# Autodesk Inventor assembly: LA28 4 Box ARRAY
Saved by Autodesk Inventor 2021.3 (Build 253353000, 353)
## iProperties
Created: 2023-01
Part Number: LA28 4 Box ARRAY
Document SubType Name: Assembly
Designer: AdminForWorker
Title: LA28 4 Box ARRAY v2
Author: AdminForWorker
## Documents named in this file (3)
- c:\worker\convert-fusion-r08-cosv3\tmp\job-1\2\output\files\38fcaebe-cb34-4e03-bd92-f432653286df\9825a87c-4a88-42d5-add3-ba31ce4555a8.iam
- c:\worker\convert-fusion-r08-cosv3\tmp\job-1\2\output\files\38fcaebe-cb34-4e03-bd92-f432653286df\LA28 RF1 Sheet Metal Assembly v3.iam
- c:\worker\convert-fusion-r08-cosv3\tmp\job-1\2\output\files\38fcaebe-cb34-4e03-bd92-f432653286df\LA28 TOUR BLOCK v2.ipt
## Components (5 placed, 2 different names)
1. LA28 RF1 Sheet Metal Assembly v3:1 [sub-assembly]
2. LA28 TOUR BLOCK v2:1
3. LA28 TOUR BLOCK v2:2
4. LA28 TOUR BLOCK v2:3
5. LA28 TOUR BLOCK v2:4
